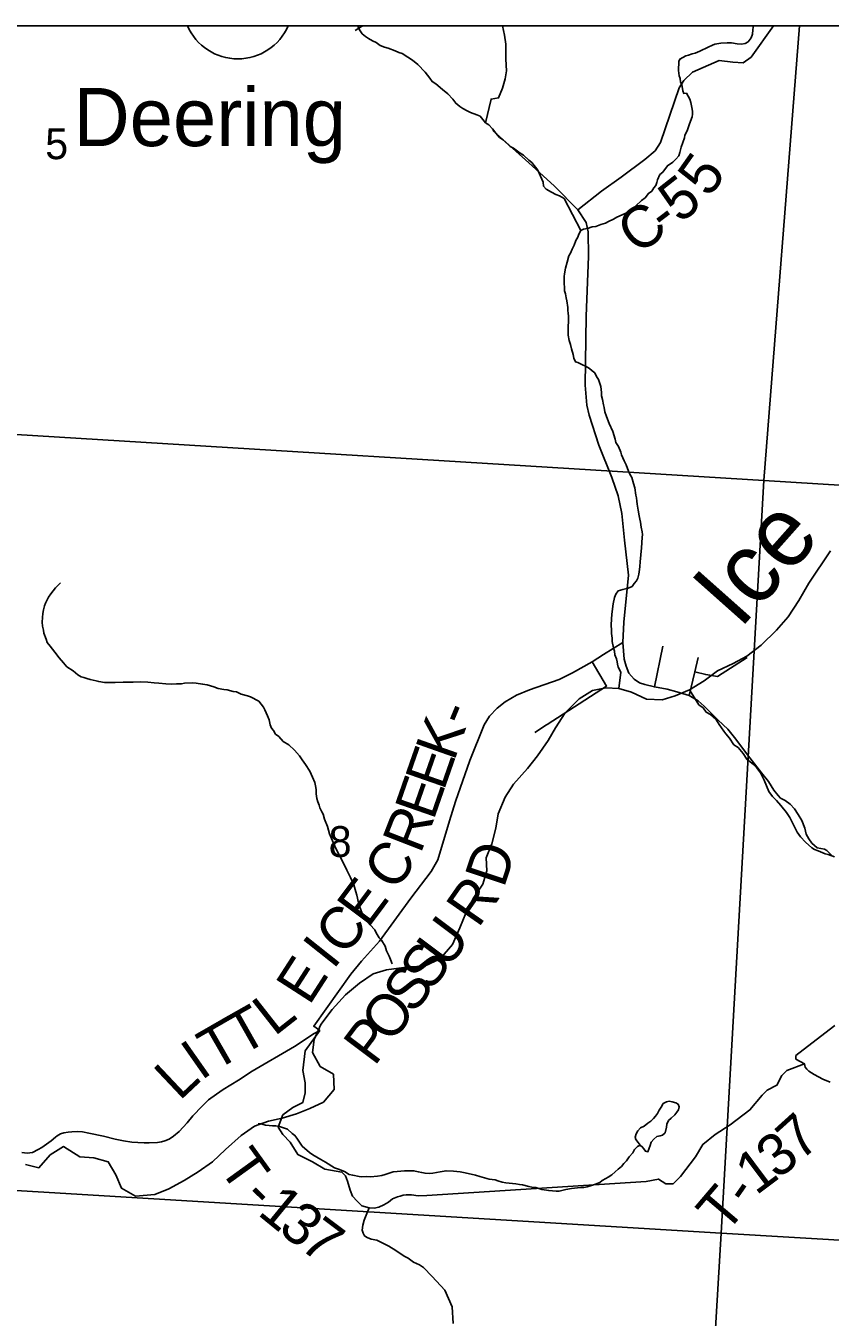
# Model space of a CAD drawing. Extents: x 0 to 45.4, y -2.2 to 22.
# Drawn here: x 4.13 to 5.221, y 19.147 to 20.9 of the extents above; entities that cross this region are included whole.
import ezdxf

# ---------------------------------------------------------------- set-up
doc = ezdxf.new("R2010")
doc.units = 0
for name, color, linetype in [('GM_X_Corporation', 7, 'Continuous'), ('GM_X_County_Road', 7, 'Continuous'), ('GM_X_County_Road_Text', 7, 'Continuous'), ('GM_X_Minor_River', 7, 'Continuous'), ('GM_X_Minor_River_Text', 7, 'Continuous'), ('GM_X_Section_Text', 7, 'Continuous'), ('GM_X_State_Route', 7, 'Continuous'), ('GM_X_Township_Road', 7, 'Continuous'), ('GM_X_Township_Road_Text', 7, 'Continuous'), ('GM_X_Unincorporated_Text', 7, 'Continuous'), ('GM_X_US_Shield', 7, 'Continuous'), ('SH_Data', 7, 'Continuous')]:
    doc.layers.add(name, color=color, linetype=linetype)

msp = doc.modelspace()

# ---------------------------------------------------------------- linework, layer by layer
at = {"layer": 'GM_X_Corporation'}
for points in [[(8.9, 20.9), (2.1, 20.9), (2.1, 19.3454), (2.1562, 19.32), (2.2951, 19.2289), (2.4503, 19.1527), (2.5862, 19.0536)], [(6.2942, 20.9), (2.1, 20.9), (2.1, 19.3454), (2.1562, 19.32), (2.2951, 19.2289), (2.4503, 19.1527), (2.5862, 19.0536)]]:
    msp.add_lwpolyline(points, dxfattribs=at)
for points in [[(5.1793, 20.9), (4.0874, 20.9), (4.0572, 20.3489), (5.1309, 20.2827)], [(6.3012, 20.9), (5.1793, 20.9), (5.1309, 20.2827), (6.2516, 20.2138)], [(4.0572, 20.3489), (5.1309, 20.2827), (5.073, 19.2613), (3.9891, 19.3268)], [(5.1309, 20.2827), (6.2516, 20.2138), (6.1827, 19.1954), (5.073, 19.2613)], [(5.073, 19.2613), (5.0121, 18.2353), (3.9206, 18.2985), (3.9891, 19.3268)], [(6.1827, 19.1954), (6.1142, 18.166), (5.0121, 18.2353), (5.073, 19.2613)]]:
    msp.add_lwpolyline(points, close=True, dxfattribs=at)
at = {"layer": 'GM_X_County_Road'}
for points in [[(4.8784, 20.6504), (4.9105, 20.6756), (4.9375, 20.6946), (4.9696, 20.7184), (4.9833, 20.7304), (4.9905, 20.7416), (5.0162, 20.8159), (5.0221, 20.8258), (5.0341, 20.837), (5.0704, 20.853), (5.089, 20.8507), (5.1027, 20.8496), (5.1137, 20.8575), (5.1438, 20.9)], [(4.1243, 19.3705), (4.1315, 19.3699), (4.1388, 19.3709), (4.1465, 19.3747), (4.1512, 19.3774), (4.1576, 19.3821), (4.1641, 19.3867), (4.1696, 19.3913), (4.1719, 19.3931), (4.1767, 19.3958), (4.1812, 19.3974), (4.1869, 19.3982), (4.192, 19.3988), (4.1993, 19.3991), (4.2065, 19.3986), (4.2152, 19.3969), (4.2349, 19.3928), (4.2508, 19.3889), (4.2621, 19.3866), (4.2734, 19.3849), (4.2816, 19.3841), (4.2901, 19.3838), (4.2969, 19.3838), (4.3081, 19.3841), (4.3136, 19.3852), (4.3182, 19.3865), (4.3242, 19.389), (4.33, 19.3927), (4.3376, 19.3994), (4.3483, 19.4108), (4.3563, 19.4206), (4.3687, 19.4335), (4.3774, 19.4421), (4.3884, 19.45), (4.3974, 19.4561), (4.4077, 19.4624), (4.4183, 19.469), (4.4367, 19.4811), (4.4943, 19.5146), (4.5208, 19.5323), (4.5283, 19.5361), (4.5201, 19.5421), (4.5704, 19.6128), (4.5851, 19.6303), (4.6096, 19.6575), (4.6521, 19.7158), (4.6793, 19.7523), (4.6886, 19.768), (4.7044, 19.8209), (4.7125, 19.847), (4.7321, 19.9026), (4.7514, 19.9511), (4.7586, 19.9629), (4.7692, 19.9738), (4.7801, 19.9824), (4.7955, 19.9916), (4.813, 19.9985), (4.8532, 20.0127), (4.8713, 20.0219), (4.8981, 20.0365), (4.9131, 20.0467), (4.9395, 20.0629)], [(5.221, 19.466), (5.211, 19.4704), (5.1991, 19.4765), (5.1921, 19.4809), (5.189, 19.4837), (5.187, 19.4865), (5.186, 19.4911), (5.1745, 19.4974), (5.1745, 19.5022), (5.1961, 19.519), (5.2272, 19.543)]]:
    msp.add_lwpolyline(points, dxfattribs=at)
at = {"layer": 'GM_X_Minor_River'}
for points in [[(4.8825, 20.6221), (4.8598, 20.6654), (4.8538, 20.6692), (4.8485, 20.6709), (4.8429, 20.6744), (4.8354, 20.6783), (4.8321, 20.6825), (4.8314, 20.6879), (4.8278, 20.6959), (4.8241, 20.7043), (4.816, 20.7147), (4.8119, 20.7178), (4.8048, 20.7244), (4.8003, 20.7271), (4.7913, 20.7341), (4.7868, 20.7361), (4.7775, 20.745), (4.7722, 20.7485), (4.7674, 20.7542), (4.7626, 20.7604), (4.7578, 20.7654), (4.7533, 20.7685), (4.7459, 20.7774), (4.7414, 20.7794), (4.7327, 20.7825), (4.7282, 20.7845), (4.7226, 20.7877), (4.7184, 20.7904), (4.7128, 20.795), (4.7088, 20.8004), (4.7021, 20.8077), (4.695, 20.8136), (4.6857, 20.8213), (4.6808, 20.8244), (4.6775, 20.829), (4.6712, 20.8371), (4.6615, 20.8475), (4.654, 20.8534), (4.6477, 20.8573), (4.6402, 20.8623), (4.6357, 20.8639), (4.6308, 20.8659), (4.621, 20.8695), (4.6161, 20.8711), (4.6104, 20.8735), (4.6048, 20.8774), (4.5999, 20.8797), (4.5947, 20.8828), (4.5906, 20.8856), (4.5861, 20.8891), (4.5831, 20.8933), (4.5806, 20.8983), (4.5799, 20.9)], [(4.7533, 20.7685), (4.7607, 20.8006), (4.7709, 20.8021), (4.7762, 20.8154), (4.78, 20.8279), (4.7815, 20.8389), (4.7808, 20.8548), (4.7808, 20.8749), (4.7789, 20.8874), (4.7762, 20.8999), (4.7762, 20.9)], [(4.8664, 20.5878), (4.8687, 20.5915), (4.8707, 20.5968), (4.8735, 20.6021), (4.8758, 20.6085), (4.8786, 20.613), (4.8798, 20.6172), (4.8825, 20.6221), (4.8863, 20.6239), (4.8917, 20.6249), (4.8981, 20.6271), (4.9027, 20.6278), (4.9096, 20.6303), (4.916, 20.6321), (4.9199, 20.6343), (4.9271, 20.6376), (4.9313, 20.6402), (4.9386, 20.6435), (4.9435, 20.6457), (4.9477, 20.6479), (4.9535, 20.652), (4.957, 20.6557), (4.9647, 20.6628), (4.9697, 20.6665), (4.9743, 20.6725), (4.9789, 20.6755), (4.9816, 20.68), (4.9844, 20.6834), (4.9856, 20.6875), (4.9868, 20.6909), (4.9899, 20.6981), (4.9938, 20.7015), (5, 20.7101), (5.0076, 20.7149), (5.0115, 20.719), (5.0154, 20.7235), (5.017, 20.728), (5.0186, 20.7352), (5.021, 20.7416), (5.023, 20.748), (5.0238, 20.7514), (5.0269, 20.7575), (5.0298, 20.7669), (5.0337, 20.7763), (5.0342, 20.7801), (5.0339, 20.7843), (5.0332, 20.7893), (5.0318, 20.7961), (5.0304, 20.8003), (5.0259, 20.8084), (5.0225, 20.808), (5.0211, 20.8119), (5.0197, 20.8202), (5.0179, 20.8237), (5.0172, 20.8283), (5.0161, 20.8321), (5.0151, 20.8393), (5.0157, 20.8515), (5.0169, 20.8548), (5.025, 20.8593), (5.0288, 20.8603), (5.0337, 20.8618), (5.0375, 20.8629), (5.044, 20.8654), (5.0555, 20.8709), (5.0612, 20.8739), (5.0646, 20.8749), (5.0726, 20.8763), (5.0813, 20.8769), (5.087, 20.8768), (5.0946, 20.8756), (5.1006, 20.8751), (5.1055, 20.8758), (5.1098, 20.8784), (5.1136, 20.8836), (5.1156, 20.8889), (5.1161, 20.8946), (5.1162, 20.898), (5.1164, 20.9)], [(4.934, 20.0007), (4.9367, 20.0227), (4.9334, 20.0296), (4.9324, 20.0334), (4.9317, 20.0369), (4.931, 20.041), (4.9288, 20.0464), (4.9281, 20.0513), (4.9267, 20.0555), (4.9253, 20.0643), (4.925, 20.0689), (4.9244, 20.0753), (4.9241, 20.0799), (4.9238, 20.0864), (4.924, 20.0951), (4.9245, 20.1011), (4.9257, 20.1087), (4.9266, 20.1155), (4.9283, 20.1242), (4.9299, 20.1284), (4.9334, 20.1329), (4.9395, 20.1351), (4.9467, 20.1368), (4.952, 20.139), (4.9548, 20.1432), (4.9582, 20.1465), (4.9598, 20.1503), (4.9614, 20.1556), (4.9623, 20.162), (4.9627, 20.1662), (4.9632, 20.1723), (4.9647, 20.1916), (4.9657, 20.2056), (4.9661, 20.2094), (4.9658, 20.2132), (4.9644, 20.2193), (4.9634, 20.2262), (4.9627, 20.2304), (4.9617, 20.2349), (4.9603, 20.2426), (4.9589, 20.2506), (4.9586, 20.2547), (4.9579, 20.2593), (4.9572, 20.2631), (4.9559, 20.273), (4.9541, 20.2787), (4.9516, 20.2871), (4.949, 20.2914), (4.9472, 20.2956), (4.944, 20.304), (4.9414, 20.3097), (4.9378, 20.3177), (4.9367, 20.3212), (4.9338, 20.3288), (4.9301, 20.3346), (4.929, 20.3388), (4.9258, 20.3495), (4.9211, 20.3602), (4.9175, 20.3697), (4.9153, 20.3762), (4.9143, 20.3819), (4.9132, 20.3854), (4.9118, 20.3926), (4.9108, 20.3979), (4.9105, 20.4021), (4.9095, 20.4105), (4.9066, 20.42), (4.904, 20.4242), (4.9015, 20.4288), (4.8981, 20.4319), (4.8944, 20.4347), (4.8899, 20.4374), (4.8839, 20.4405), (4.8786, 20.4429), (4.8752, 20.4437), (4.873, 20.4487), (4.872, 20.454), (4.8698, 20.4617), (4.8684, 20.4674), (4.8666, 20.4727), (4.8656, 20.48), (4.8653, 20.4841), (4.8657, 20.5062), (4.8654, 20.5096), (4.8651, 20.5141), (4.8651, 20.5176), (4.8638, 20.5267), (4.8627, 20.5309), (4.8617, 20.5362), (4.8606, 20.5404), (4.8603, 20.5457), (4.86, 20.5492), (4.8598, 20.556), (4.8598, 20.5598), (4.8603, 20.5632), (4.8619, 20.5711), (4.864, 20.5791), (4.8664, 20.5878)], [(4.5184, 19.5065), (4.5208, 19.524), (4.5299, 19.5444), (4.5452, 19.5649), (4.5634, 19.5845), (4.5824, 19.6004), (4.6007, 19.6132), (4.6189, 19.6185), (4.6492, 19.6229), (4.6704, 19.6236), (4.6916, 19.6334), (4.7084, 19.6531), (4.7183, 19.6758), (4.7267, 19.6955), (4.7374, 19.7168), (4.7496, 19.7349), (4.755, 19.7531), (4.7543, 19.7706), (4.762, 19.7895), (4.7674, 19.8108), (4.7705, 19.8305), (4.7797, 19.8532), (4.7911, 19.8707), (4.8101, 19.8919), (4.8238, 19.9093), (4.8383, 19.9297), (4.8482, 19.9471), (4.8612, 19.9676), (4.8802, 19.9865), (4.8984, 19.9978), (4.9166, 20.0015), (4.934, 20.0007), (4.9514, 19.9954), (4.9718, 19.9862), (4.993, 19.9853), (5.0105, 19.9906), (5.0302, 19.9989), (5.05, 20.0109), (5.0682, 20.0246), (5.0894, 20.0343), (5.1076, 20.0442), (5.1274, 20.0593), (5.1479, 20.0797), (5.1639, 20.0979), (5.1784, 20.1198), (5.1921, 20.1433), (5.2211, 20.1872)], [(4.1516, 20.0907), (4.1521, 20.0971), (4.1525, 20.1021), (4.1534, 20.1074), (4.155, 20.1127), (4.1562, 20.1164), (4.1605, 20.1247), (4.1633, 20.1292), (4.1667, 20.133), (4.1698, 20.1371), (4.1733, 20.1408), (4.1768, 20.1438)], [(4.6267, 19.627), (4.6242, 19.6327), (4.6227, 19.6373), (4.6191, 19.6446), (4.6169, 19.6507), (4.6121, 19.6587), (4.6088, 19.6622), (4.6051, 19.6687), (4.6029, 19.673), (4.5966, 19.6799), (4.5907, 19.6876), (4.5859, 19.6949), (4.5823, 19.7052), (4.5808, 19.7098), (4.5788, 19.7201), (4.5773, 19.7243), (4.5744, 19.7338), (4.5701, 19.7438), (4.5653, 19.7537), (4.5606, 19.7633), (4.5554, 19.7729), (4.5503, 19.7832), (4.5456, 19.7939), (4.5416, 19.8031), (4.5387, 19.813), (4.5347, 19.823), (4.533, 19.8298), (4.5311, 19.8333), (4.5286, 19.8386), (4.5275, 19.8421), (4.5257, 19.8466), (4.5246, 19.8512), (4.5236, 19.8577), (4.5233, 19.8634), (4.5227, 19.8683), (4.5216, 19.8729), (4.5187, 19.8802), (4.5147, 19.8882), (4.5092, 19.8974), (4.5043, 19.9036), (4.501, 19.909), (4.4943, 19.9167), (4.4865, 19.924), (4.4786, 19.9287), (4.4727, 19.9353), (4.4682, 19.9387), (4.4656, 19.9434), (4.4627, 19.9468), (4.4612, 19.951), (4.4595, 19.9579), (4.4573, 19.9636), (4.4555, 19.9674), (4.454, 19.9716), (4.4522, 19.9751), (4.4455, 19.9832), (4.4346, 19.9891), (4.4301, 19.9907), (4.4218, 19.9927), (4.4154, 19.9958), (4.4109, 19.9963), (4.4026, 19.9987), (4.3981, 19.9992), (4.3905, 20.0004), (4.3845, 20.0028), (4.3755, 20.0053), (4.3694, 20.0065), (4.3607, 20.0078), (4.3558, 20.0082), (4.3448, 20.0077), (4.3406, 20.007), (4.3338, 20.0067), (4.3274, 20.0065), (4.3194, 20.007), (4.31, 20.0079), (4.3035, 20.0084), (4.2952, 20.0089), (4.2854, 20.0094), (4.2751, 20.0092), (4.2717, 20.0093), (4.2615, 20.0091), (4.2509, 20.0085), (4.2365, 20.0088), (4.2286, 20.01), (4.2252, 20.0108), (4.2169, 20.0129), (4.2124, 20.0141), (4.2082, 20.0153), (4.2048, 20.0165), (4.2003, 20.0192), (4.1936, 20.0243), (4.1854, 20.0301), (4.1809, 20.0355), (4.175, 20.0421), (4.1687, 20.0498), (4.1628, 20.0578), (4.1583, 20.0629), (4.1572, 20.0674), (4.154, 20.0755), (4.1537, 20.0796), (4.1522, 20.085), (4.1516, 20.0907)], [(5.0302, 19.9989), (5.0428, 19.9784), (5.0484, 19.9741), (5.0528, 19.9684), (5.0584, 19.9652), (5.0659, 19.9587), (5.0703, 19.9517), (5.0766, 19.9425), (5.0792, 19.9391), (5.0844, 19.9329), (5.0903, 19.9241), (5.0959, 19.9202), (5.1026, 19.9125), (5.1077, 19.9044), (5.1167, 19.8974), (5.1208, 19.8932), (5.1264, 19.8859), (5.1285, 19.8817), (5.1315, 19.8759), (5.1344, 19.8683), (5.1376, 19.8606), (5.1425, 19.8537), (5.148, 19.8483), (5.154, 19.8417), (5.1614, 19.8321), (5.1662, 19.8252), (5.1709, 19.8153), (5.1761, 19.8053), (5.1805, 19.7992), (5.1876, 19.7918), (5.1961, 19.7841), (5.1995, 19.7818), (5.2044, 19.7802), (5.2078, 19.779), (5.2142, 19.7762), (5.218, 19.775), (5.2266, 19.7722)], [(4.1293, 19.3546), (4.1474, 19.35), (4.1626, 19.3674), (4.1809, 19.3787), (4.2028, 19.365), (4.2217, 19.3634), (4.2414, 19.358), (4.2519, 19.3405), (4.2594, 19.3222), (4.2783, 19.3115), (4.3048, 19.3137), (4.3238, 19.3212), (4.3443, 19.3326), (4.3632, 19.3446), (4.383, 19.3582), (4.4005, 19.3749), (4.4218, 19.3938), (4.44, 19.4066), (4.459, 19.4134), (4.4772, 19.4171), (4.4969, 19.4231), (4.5151, 19.4306), (4.5333, 19.4389), (4.5478, 19.4563), (4.5471, 19.4768), (4.529, 19.4875), (4.5184, 19.5065)], [(4.4449, 19.4098), (4.4483, 19.4094), (4.4547, 19.4078), (4.4596, 19.4073), (4.4641, 19.4069), (4.4687, 19.4068), (4.4736, 19.4059), (4.4804, 19.4039), (4.4845, 19.4023), (4.4909, 19.3965), (4.4946, 19.3938), (4.4972, 19.3903), (4.5046, 19.3792), (4.5143, 19.3707), (4.5191, 19.3676), (4.5296, 19.3613), (4.536, 19.3574), (4.5484, 19.35), (4.5536, 19.348), (4.5619, 19.3448), (4.5683, 19.3409), (4.5732, 19.3397), (4.5819, 19.338), (4.5853, 19.3376), (4.5921, 19.3379), (4.597, 19.3378), (4.6065, 19.3384), (4.6126, 19.3394), (4.6171, 19.3408), (4.6278, 19.3445), (4.6335, 19.3451), (4.6434, 19.3457), (4.6468, 19.346), (4.6562, 19.3459), (4.6619, 19.3446), (4.6668, 19.3434), (4.6713, 19.3426), (4.6774, 19.3421), (4.6819, 19.3428), (4.6918, 19.3445), (4.6998, 19.3459), (4.7096, 19.3454), (4.7187, 19.3444), (4.7255, 19.3432), (4.7395, 19.3399), (4.7455, 19.3383), (4.7583, 19.3347), (4.7662, 19.3334), (4.77, 19.3322), (4.776, 19.3306), (4.781, 19.3297), (4.7942, 19.328), (4.7995, 19.3271), (4.8036, 19.3267), (4.8119, 19.3246), (4.8161, 19.3238), (4.8217, 19.323), (4.8297, 19.3205), (4.8391, 19.3189), (4.8493, 19.3183), (4.8531, 19.3183), (4.8622, 19.3204), (4.8698, 19.3218), (4.874, 19.3225), (4.8782, 19.3228), (4.8827, 19.3234), (4.8865, 19.3234), (4.8911, 19.3241), (4.8972, 19.3259), (4.9025, 19.3277), (4.9082, 19.3299), (4.9117, 19.3325), (4.9163, 19.3354), (4.9197, 19.3373), (4.9247, 19.3406), (4.9293, 19.3443), (4.9332, 19.348), (4.9378, 19.3518), (4.9409, 19.3559), (4.9447, 19.3596), (4.9482, 19.3649), (4.9533, 19.3701), (4.9552, 19.3746), (4.9595, 19.3787), (4.9629, 19.3806), (4.9603, 19.3844), (4.9574, 19.3883), (4.9563, 19.3917), (4.9575, 19.3959), (4.9598, 19.4), (4.9637, 19.4041), (4.9683, 19.4063), (4.9737, 19.4104), (4.9775, 19.4134), (4.9813, 19.4167), (4.9841, 19.4201), (4.9864, 19.4235), (4.9887, 19.428), (4.9915, 19.4321), (4.9942, 19.437), (4.9988, 19.4396)], [(4.9988, 19.4396), (5.0022, 19.4403), (5.0067, 19.4394), (5.0113, 19.4379), (5.0146, 19.4363), (5.0161, 19.4328), (5.0149, 19.4287), (5.0129, 19.4253), (5.0102, 19.4219), (5.0052, 19.4174), (5.0014, 19.4141), (4.9994, 19.4092), (4.9986, 19.405), (4.9969, 19.3975), (4.9934, 19.3941), (4.99, 19.3934), (4.9858, 19.3923), (4.9816, 19.389), (4.9781, 19.3849), (4.9765, 19.3803), (4.9753, 19.3766), (4.9737, 19.3717), (4.9703, 19.3725), (4.9666, 19.3775), (4.9629, 19.3806)]]:
    msp.add_lwpolyline(points, dxfattribs=at)
at = {"layer": 'GM_X_State_Route'}
msp.add_lwpolyline([(4.7633, 20.7579), (4.7677, 20.7539), (4.8165, 20.7101), (4.8469, 20.6822), (4.8784, 20.6504), (4.89, 20.6329), (4.8927, 20.6203), (4.8929, 20.5869), (4.89, 20.5059), (4.8886, 20.4124), (4.8905, 20.3852), (4.894, 20.3713), (4.9072, 20.3309), (4.9245, 20.2868), (4.9334, 20.2622), (4.9384, 20.2382), (4.9418, 20.2019), (4.9473, 20.1544), (4.9408, 20.0907), (4.9395, 20.0629), (4.9415, 20.0402), (4.944, 20.0306), (4.9475, 20.0215), (4.955, 20.0131), (4.9623, 20.0084), (4.9694, 20.006), (4.9823, 20.0026), (4.9999, 19.9997), (5.0128, 19.9961), (5.0296, 19.991), (5.0416, 19.9836), (5.0497, 19.9766), (5.0688, 19.9576), (5.0821, 19.9452), (5.0929, 19.9316), (5.1087, 19.9104), (5.1279, 19.8862), (5.1373, 19.8741), (5.1443, 19.8627), (5.1503, 19.8551), (5.1536, 19.8517), (5.1599, 19.8486), (5.1668, 19.8433), (5.1726, 19.8373), (5.1776, 19.8295), (5.1822, 19.8215), (5.1866, 19.8108), (5.1883, 19.8027), (5.1917, 19.7965), (5.1959, 19.7907), (5.2031, 19.7841), (5.2133, 19.7824), (5.2162, 19.7805), (5.2241, 19.773)], dxfattribs=at)
at = {"layer": 'GM_X_Township_Road'}
for p, q in [((4.9823, 20.0026), (4.9938, 20.058)), ((4.8202, 19.941), (4.8359, 19.9513))]:
    msp.add_line(p, q, dxfattribs=at)
for points in [[(4.5762, 20.8937), (4.5849, 20.8991), (4.5874, 20.9)], [(4.8359, 19.9513), (4.8367, 19.9518), (4.9174, 20.0037), (4.8981, 20.0365)], [(5.0296, 19.991), (5.0372, 20.0231), (5.0417, 20.0426)], [(5.0372, 20.0231), (5.052, 20.0194), (5.0679, 20.0169), (5.1084, 20.0428)], [(4.5283, 19.5361), (4.5085, 19.5089), (4.5052, 19.4821), (4.5085, 19.4653), (4.5085, 19.4519), (4.5052, 19.4385), (4.4918, 19.4318), (4.4784, 19.4218), (4.4717, 19.405), (4.4784, 19.395), (4.4884, 19.3849), (4.4985, 19.3681), (4.5186, 19.3581), (4.5354, 19.3481), (4.5584, 19.3441), (4.5635, 19.339), (4.5659, 19.3316), (4.5694, 19.3194), (4.5728, 19.3114), (4.579, 19.3047), (4.5856, 19.2982), (4.5955, 19.2955)], [(5.008, 19.328), (5.018, 19.338), (5.0381, 19.3648), (5.0482, 19.3816), (5.0649, 19.395), (5.0851, 19.4084), (5.1119, 19.4285), (5.1286, 19.4486), (5.1353, 19.4553), (5.1487, 19.462), (5.1554, 19.4754), (5.1622, 19.4821), (5.186, 19.4911)], [(4.5955, 19.2955), (4.602, 19.2952), (4.6086, 19.2964), (4.6151, 19.2998), (4.6217, 19.3034), (4.6272, 19.3076), (4.6337, 19.3103), (4.6374, 19.3115), (4.6415, 19.3127), (4.6458, 19.3131), (4.6529, 19.3131), (4.662, 19.3119), (4.6735, 19.3122), (4.9711, 19.3313), (4.9879, 19.3347), (4.9979, 19.328), (5.0009, 19.328), (5.008, 19.328)], [(4.7094, 19.1385), (4.7079, 19.1613), (4.698, 19.1838), (4.681, 19.2026), (4.6692, 19.2147), (4.6637, 19.2184), (4.6556, 19.2217), (4.6482, 19.2273), (4.6431, 19.2302), (4.6317, 19.2378), (4.6221, 19.2435), (4.6121, 19.2486), (4.6059, 19.2516), (4.5981, 19.2531), (4.5928, 19.2551), (4.5889, 19.2575), (4.5871, 19.2612), (4.5858, 19.2654), (4.5868, 19.272), (4.5885, 19.2788), (4.5923, 19.2877), (4.5955, 19.2955)]]:
    msp.add_lwpolyline(points, dxfattribs=at)
at = {"layer": 'GM_X_US_Shield'}
msp.add_line((4.4856, 20.9), (4.3489, 20.9), dxfattribs=at)
msp.add_arc((4.4172, 20.9295), 0.0744, 203.33, 336.67, dxfattribs=at)
at = {"layer": 'SH_Data'}
msp.add_line((2.1, 20.9), (8.9, 20.9), dxfattribs=at)

# ---------------------------------------------------------------- texts
at = {"layer": 'GM_X_County_Road_Text'}
for s, rotation, p in [('5', 54.7675, (5.0567, 20.6654)), ('5', 38.1921, (5.0168, 20.6308)), ('C', 37.1119, (4.9601, 20.5878)), ('-', 37.2571, (4.9975, 20.6161)), ('-', 67.3636, (4.727, 19.947)), ('K', 70.5167, (4.7106, 19.9006)), ('E', 70.7719, (4.6966, 19.8606)), ('E', 70.8018, (4.6826, 19.8204)), ('R', 68.7527, (4.665, 19.7749)), ('C', 54.1302, (4.6301, 19.7232)), ('D', 71.6329, (4.778, 19.7285)), ('E', 53.2291, (4.5937, 19.6742)), ('R', 55.1087, (4.7433, 19.6742)), ('C', 49.2435, (4.5606, 19.6355)), ('U', 53.1547, (4.7016, 19.6184)), ('I', 51.5328, (4.5464, 19.6177)), ('S', 53.0549, (4.6785, 19.5877)), ('E', 57.223, (4.514, 19.569)), ('S', 53.0312, (4.6555, 19.5571)), ('L', 38.1674, (4.4668, 19.5275)), ('O', 53.0349, (4.6254, 19.5171)), ('T', 29.4911, (4.422, 19.5014)), ('T', 29.9103, (4.3853, 19.4802)), ('P', 53.0357, (4.6024, 19.4865)), ('I', 34.993, (4.3673, 19.4676)), ('L', 43.3183, (4.338, 19.4398))]:
    msp.add_text(s, height=0.0568, rotation=rotation, dxfattribs=at).set_placement(p)
at = {"layer": 'GM_X_Minor_River_Text'}
msp.add_text('Ice', height=0.09469, rotation=48.3463, dxfattribs=at).set_placement((5.0979, 20.0795))
at = {"layer": 'GM_X_Section_Text'}
for s, p in [('5', (4.1558, 20.719)), ('8', (4.5404, 19.7718))]:
    msp.add_text(s, height=0.0419, rotation=0, dxfattribs=at).set_placement(p)
at = {"layer": 'GM_X_Township_Road_Text'}
for s, rotation, p in [('7', 42.1376, (5.1803, 19.3576)), ('3', 37.7367, (5.1489, 19.3332)), ('T', 305.8081, (4.3899, 19.35)), ('1', 36.7731, (5.1201, 19.3116)), ('-', 315.3172, (4.4215, 19.3077)), ('1', 320.7415, (4.4424, 19.2874)), ('T', 49.6158, (5.0789, 19.2588)), ('-', 55.1548, (5.1101, 19.2959)), ('3', 321.3518, (4.47, 19.2648)), ('7', 323.0415, (4.4988, 19.2418))]:
    msp.add_text(s, height=0.0568, rotation=rotation, dxfattribs=at).set_placement(p)
at = {"layer": 'GM_X_Unincorporated_Text'}
msp.add_text('Deering', height=0.07898, rotation=0, dxfattribs=at).set_placement((4.1942, 20.7367))

doc.saveas('drawing.dxf')
